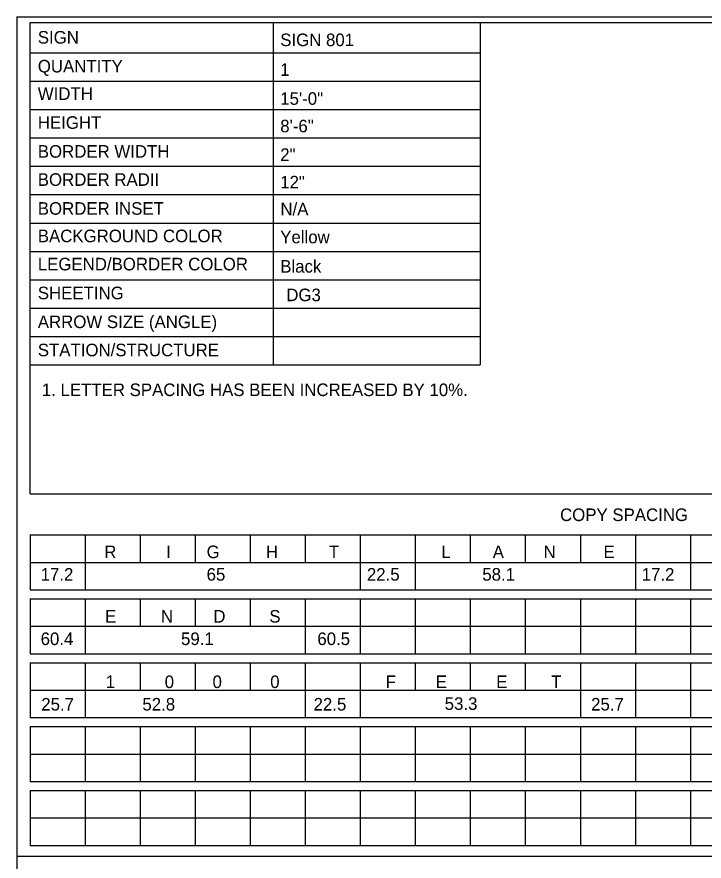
# Model space of a CAD drawing. Extents: x 10268147 to 10268469, y 2141099 to 2141204.
# Drawn here: x 10268153.14 to 10268191.41, y 2141156.92 to 2141203.96 of the extents above; entities that cross this region are included whole.
import ezdxf

# ---------------------------------------------------------------- set-up
doc = ezdxf.new("R2010")
doc.units = 0
for name, color, linetype in [('61', 7, 'Continuous'), ('North Arrow', 7, 'Continuous'), ('SheetLinesMisc2_dp', 7, 'Continuous'), ('TextMisc', 7, 'Continuous')]:
    doc.layers.add(name, color=color, linetype=linetype)

msp = doc.modelspace()

# ---------------------------------------------------------------- linework, layer by layer
at = {"layer": '61'}
for p, q in [((10268153.875, 2141203.638), (10268229.209, 2141203.638)), ((10268153.875, 2141177.389), (10268153.875, 2141203.638)), ((10268167.411, 2141203.638), (10268167.411, 2141184.572)), ((10268178.947, 2141203.638), (10268178.947, 2141184.572)), ((10268153.875, 2141201.949), (10268178.947, 2141201.949)), ((10268153.875, 2141200.37), (10268178.947, 2141200.37)), ((10268153.875, 2141198.79), (10268178.947, 2141198.79)), ((10268153.875, 2141197.21), (10268178.947, 2141197.21)), ((10268153.875, 2141195.63), (10268178.947, 2141195.63)), ((10268153.875, 2141194.051), (10268178.947, 2141194.051)), ((10268153.875, 2141192.471), (10268178.947, 2141192.471)), ((10268153.875, 2141190.891), (10268178.947, 2141190.891)), ((10268153.875, 2141189.311), (10268178.947, 2141189.311)), ((10268153.875, 2141187.731), (10268178.947, 2141187.731)), ((10268153.875, 2141186.152), (10268178.947, 2141186.152)), ((10268153.875, 2141184.572), (10268178.947, 2141184.572)), ((10268153.875, 2141177.389), (10268229.209, 2141177.389)), ((10268153.875, 2141175.094), (10268229.209, 2141175.094)), ((10268153.875, 2141175.094), (10268153.875, 2141172.034)), ((10268156.94, 2141175.094), (10268156.94, 2141172.034)), ((10268160.004, 2141175.094), (10268160.004, 2141173.564)), ((10268163.068, 2141175.094), (10268163.068, 2141173.564)), ((10268166.133, 2141175.094), (10268166.133, 2141173.564)), ((10268169.197, 2141175.094), (10268169.197, 2141173.564)), ((10268172.263, 2141175.094), (10268172.263, 2141172.034)), ((10268175.327, 2141175.094), (10268175.327, 2141172.034)), ((10268178.391, 2141175.094), (10268178.391, 2141173.564)), ((10268181.456, 2141175.094), (10268181.456, 2141173.564)), ((10268184.521, 2141175.094), (10268184.521, 2141173.564)), ((10268187.585, 2141175.094), (10268187.585, 2141172.034)), ((10268190.65, 2141175.094), (10268190.65, 2141172.034)), ((10268153.875, 2141173.564), (10268218.232, 2141173.564)), ((10268153.875, 2141172.034), (10268229.209, 2141172.034)), ((10268153.875, 2141171.535), (10268229.209, 2141171.535)), ((10268153.875, 2141171.535), (10268153.875, 2141168.475)), ((10268156.94, 2141171.535), (10268156.94, 2141168.475)), ((10268160.004, 2141171.535), (10268160.004, 2141170.005)), ((10268163.068, 2141171.535), (10268163.068, 2141170.005)), ((10268166.133, 2141171.535), (10268166.133, 2141170.005)), ((10268169.197, 2141171.535), (10268169.197, 2141168.475)), ((10268172.263, 2141171.535), (10268172.263, 2141168.475)), ((10268175.327, 2141171.535), (10268175.327, 2141168.475)), ((10268178.391, 2141171.535), (10268178.391, 2141168.475)), ((10268181.456, 2141171.535), (10268181.456, 2141168.475)), ((10268184.521, 2141171.535), (10268184.521, 2141168.475)), ((10268187.585, 2141171.535), (10268187.585, 2141168.475)), ((10268190.65, 2141171.535), (10268190.65, 2141168.475)), ((10268153.875, 2141170.005), (10268218.232, 2141170.005)), ((10268153.875, 2141168.475), (10268229.209, 2141168.475)), ((10268153.875, 2141167.976), (10268229.209, 2141167.976)), ((10268153.875, 2141167.976), (10268153.875, 2141164.915)), ((10268156.94, 2141167.976), (10268156.94, 2141164.915)), ((10268160.004, 2141167.976), (10268160.004, 2141166.445)), ((10268163.068, 2141167.976), (10268163.068, 2141166.445)), ((10268166.133, 2141167.976), (10268166.133, 2141166.445)), ((10268169.197, 2141167.976), (10268169.197, 2141164.915)), ((10268172.263, 2141167.976), (10268172.263, 2141164.915)), ((10268175.327, 2141167.976), (10268175.327, 2141166.445)), ((10268178.391, 2141167.976), (10268178.391, 2141166.445)), ((10268181.456, 2141167.976), (10268181.456, 2141166.445)), ((10268184.521, 2141167.976), (10268184.521, 2141164.915)), ((10268187.585, 2141167.976), (10268187.585, 2141164.915)), ((10268190.65, 2141167.976), (10268190.65, 2141164.915)), ((10268153.875, 2141166.445), (10268218.232, 2141166.445)), ((10268153.875, 2141164.915), (10268229.209, 2141164.915)), ((10268153.875, 2141164.416), (10268229.209, 2141164.416)), ((10268153.875, 2141164.416), (10268153.875, 2141161.355)), ((10268156.94, 2141164.416), (10268156.94, 2141161.355)), ((10268160.004, 2141164.416), (10268160.004, 2141161.355)), ((10268163.068, 2141164.416), (10268163.068, 2141161.355)), ((10268166.133, 2141164.416), (10268166.133, 2141161.355)), ((10268169.197, 2141164.416), (10268169.197, 2141161.355)), ((10268172.263, 2141164.416), (10268172.263, 2141161.355)), ((10268175.327, 2141164.416), (10268175.327, 2141161.355)), ((10268178.391, 2141164.416), (10268178.391, 2141161.355)), ((10268181.456, 2141164.416), (10268181.456, 2141161.355)), ((10268184.521, 2141164.416), (10268184.521, 2141161.355)), ((10268187.585, 2141164.416), (10268187.585, 2141161.355)), ((10268190.65, 2141164.416), (10268190.65, 2141161.355)), ((10268153.875, 2141162.886), (10268218.232, 2141162.886)), ((10268153.875, 2141161.355), (10268229.209, 2141161.355)), ((10268153.875, 2141160.856), (10268229.209, 2141160.856)), ((10268153.875, 2141160.856), (10268153.875, 2141157.796)), ((10268156.94, 2141160.856), (10268156.94, 2141157.796)), ((10268160.004, 2141160.856), (10268160.004, 2141157.796)), ((10268163.068, 2141160.856), (10268163.068, 2141157.796)), ((10268166.133, 2141160.856), (10268166.133, 2141157.796)), ((10268169.197, 2141160.856), (10268169.197, 2141157.796)), ((10268172.263, 2141160.856), (10268172.263, 2141157.796)), ((10268175.327, 2141160.856), (10268175.327, 2141157.796)), ((10268178.391, 2141160.856), (10268178.391, 2141157.796)), ((10268181.456, 2141160.856), (10268181.456, 2141157.796)), ((10268184.521, 2141160.856), (10268184.521, 2141157.796)), ((10268187.585, 2141160.856), (10268187.585, 2141157.796)), ((10268190.65, 2141160.856), (10268190.65, 2141157.796)), ((10268153.875, 2141159.327), (10268218.232, 2141159.327)), ((10268153.875, 2141157.796), (10268229.209, 2141157.796))]:
    msp.add_line(p, q, dxfattribs=at)
at = {"layer": 'SheetLinesMisc2_dp'}
for p, q in [((10268153.14, 2141203.955), (10268306.32, 2141203.955)), ((10268153.14, 2141203.955), (10268153.14, 2141108.602)), ((10268153.14, 2141157.195), (10268306.32, 2141157.195))]:
    msp.add_line(p, q, dxfattribs=at)

# ---------------------------------------------------------------- texts
at = {"layer": 'North Arrow'}
for s, p in [('SIGN 801', (10268167.807, 2141202.326)), ('1', (10268167.807, 2141200.671)), ('15\'-0"', (10268167.807, 2141199.056)), ('8\'-6"', (10268167.807, 2141197.524)), ('2"', (10268167.807, 2141195.93)), ('12"', (10268167.807, 2141194.398)), ('N/A', (10268167.817, 2141192.899)), ('Yellow', (10268167.807, 2141191.342)), ('Black', (10268167.807, 2141189.707)), ('R', (10268158.006, 2141173.8)), ('I', (10268161.456, 2141173.8)), ('G', (10268163.706, 2141173.8)), ('H', (10268167.01, 2141173.8)), ('T', (10268170.516, 2141173.8)), ('L', (10268176.774, 2141173.8)), ('A', (10268179.642, 2141173.8)), ('N', (10268182.474, 2141173.8)), ('E', (10268185.81, 2141173.8)), ('17.2', (10268154.462, 2141172.547)), ('65', (10268163.706, 2141172.547)), ('22.5', (10268172.633, 2141172.547)), ('58.1', (10268179.061, 2141172.547)), ('17.2', (10268187.937, 2141172.547)), ('E', (10268158.052, 2141170.21)), ('N', (10268161.157, 2141170.21)), ('D', (10268164.081, 2141170.21)), ('S', (10268167.2, 2141170.21)), ('60.4', (10268154.462, 2141168.958)), ('59.1', (10268162.281, 2141168.958)), ('60.5', (10268169.874, 2141168.958)), ('1', (10268158.086, 2141166.563)), ('0', (10268161.371, 2141166.563)), ('0', (10268164.036, 2141166.563)), ('0', (10268167.249, 2141166.563)), ('F', (10268173.679, 2141166.563)), ('E', (10268176.465, 2141166.563)), ('E', (10268179.833, 2141166.563)), ('T', (10268182.894, 2141166.563)), ('25.7', (10268154.498, 2141165.311)), ('52.8', (10268160.13, 2141165.311)), ('22.5', (10268169.664, 2141165.311)), ('53.3', (10268176.966, 2141165.346)), ('25.7', (10268185.12, 2141165.311))]:
    msp.add_text(s, height=0.7, dxfattribs=at).set_placement(p)
at = {"layer": 'TextMisc'}
for s, p in [('SIGN', (10268154.305, 2141202.467)), ('QUANTITY', (10268154.305, 2141200.858)), ('WIDTH', (10268154.305, 2141199.327)), ('HEIGHT', (10268154.305, 2141197.719)), ('BORDER WIDTH', (10268154.305, 2141196.111)), ('BORDER RADII', (10268154.305, 2141194.542)), ('BORDER INSET', (10268154.305, 2141192.933)), ('BACKGROUND COLOR', (10268154.305, 2141191.402)), ('LEGEND/BORDER COLOR', (10268154.305, 2141189.833)), ('SHEETING', (10268154.305, 2141188.225)), ('DG3', (10268168.143, 2141188.116)), ('ARROW SIZE (ANGLE)', (10268154.305, 2141186.617)), ('STATION/STRUCTURE', (10268154.305, 2141185.047)), ('1. LETTER SPACING HAS BEEN INCREASED BY 10%.', (10268154.531, 2141182.83)), ('COPY SPACING', (10268183.391, 2141175.867))]:
    msp.add_text(s, height=0.7, dxfattribs=at).set_placement(p)

doc.saveas('drawing.dxf')
